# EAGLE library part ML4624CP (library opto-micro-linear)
FIBER OPTIC DATA QUANTIZER
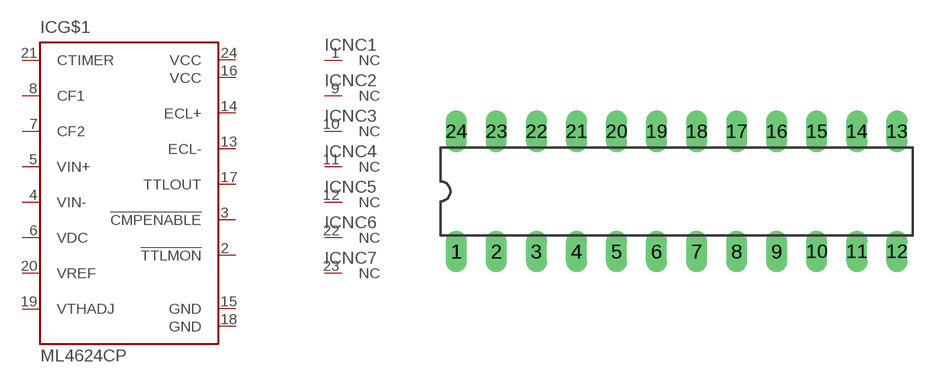
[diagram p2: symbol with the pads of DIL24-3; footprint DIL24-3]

Designator prefix IC; gates G$1=ML4624 NC1=NC NC2=NC NC3=NC NC4=NC NC5=NC NC6=NC NC7=NC

## ML4624CP (OC_FARNELL: unknown; OC_NEWARK: unknown)  [DIL24-3]
1  NC1:NC  nc
2  G$1:!TTLMON  out
3  G$1:!CMPENABLE  in
4  G$1:VIN-  in
5  G$1:VIN+  in
6  G$1:VDC  pas
7  G$1:CF2  pas
8  G$1:CF1  pas
9  NC2:NC  nc
10  NC3:NC  nc
11  NC4:NC  nc
12  NC5:NC  nc
13  G$1:ECL-  out
14  G$1:ECL+  out
15  G$1:GND  pwr
16  G$1:VCC  pwr
17  G$1:TTLOUT  out
18  G$1:GND  pwr
19  G$1:VTHADJ  in
20  G$1:VREF  in
21  G$1:CTIMER  pas
22  NC6:NC  nc
23  NC7:NC  nc
24  G$1:VCC  pwr

## Footprint DIL24-3 (pad centres in mm)
Dual In Line Package 0.3 inch
drill 0.813 long: 1 -13.97,-3.81; 2 -11.43,-3.81; 3 -8.89,-3.81; 4 -6.35,-3.81; 5 -3.81,-3.81; 6 -1.27,-3.81; 7 1.27,-3.81; 8 3.81,-3.81; 9 6.35,-3.81; 10 8.89,-3.81; 11 11.43,-3.81; 12 13.97,-3.81; 13 13.97,3.81; 14 11.43,3.81; 15 8.89,3.81; 16 6.35,3.81; 17 3.81,3.81; 18 1.27,3.81; 19 -1.27,3.81; 20 -3.81,3.81; 21 -6.35,3.81; 22 -8.89,3.81; 23 -11.43,3.81; 24 -13.97,3.81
